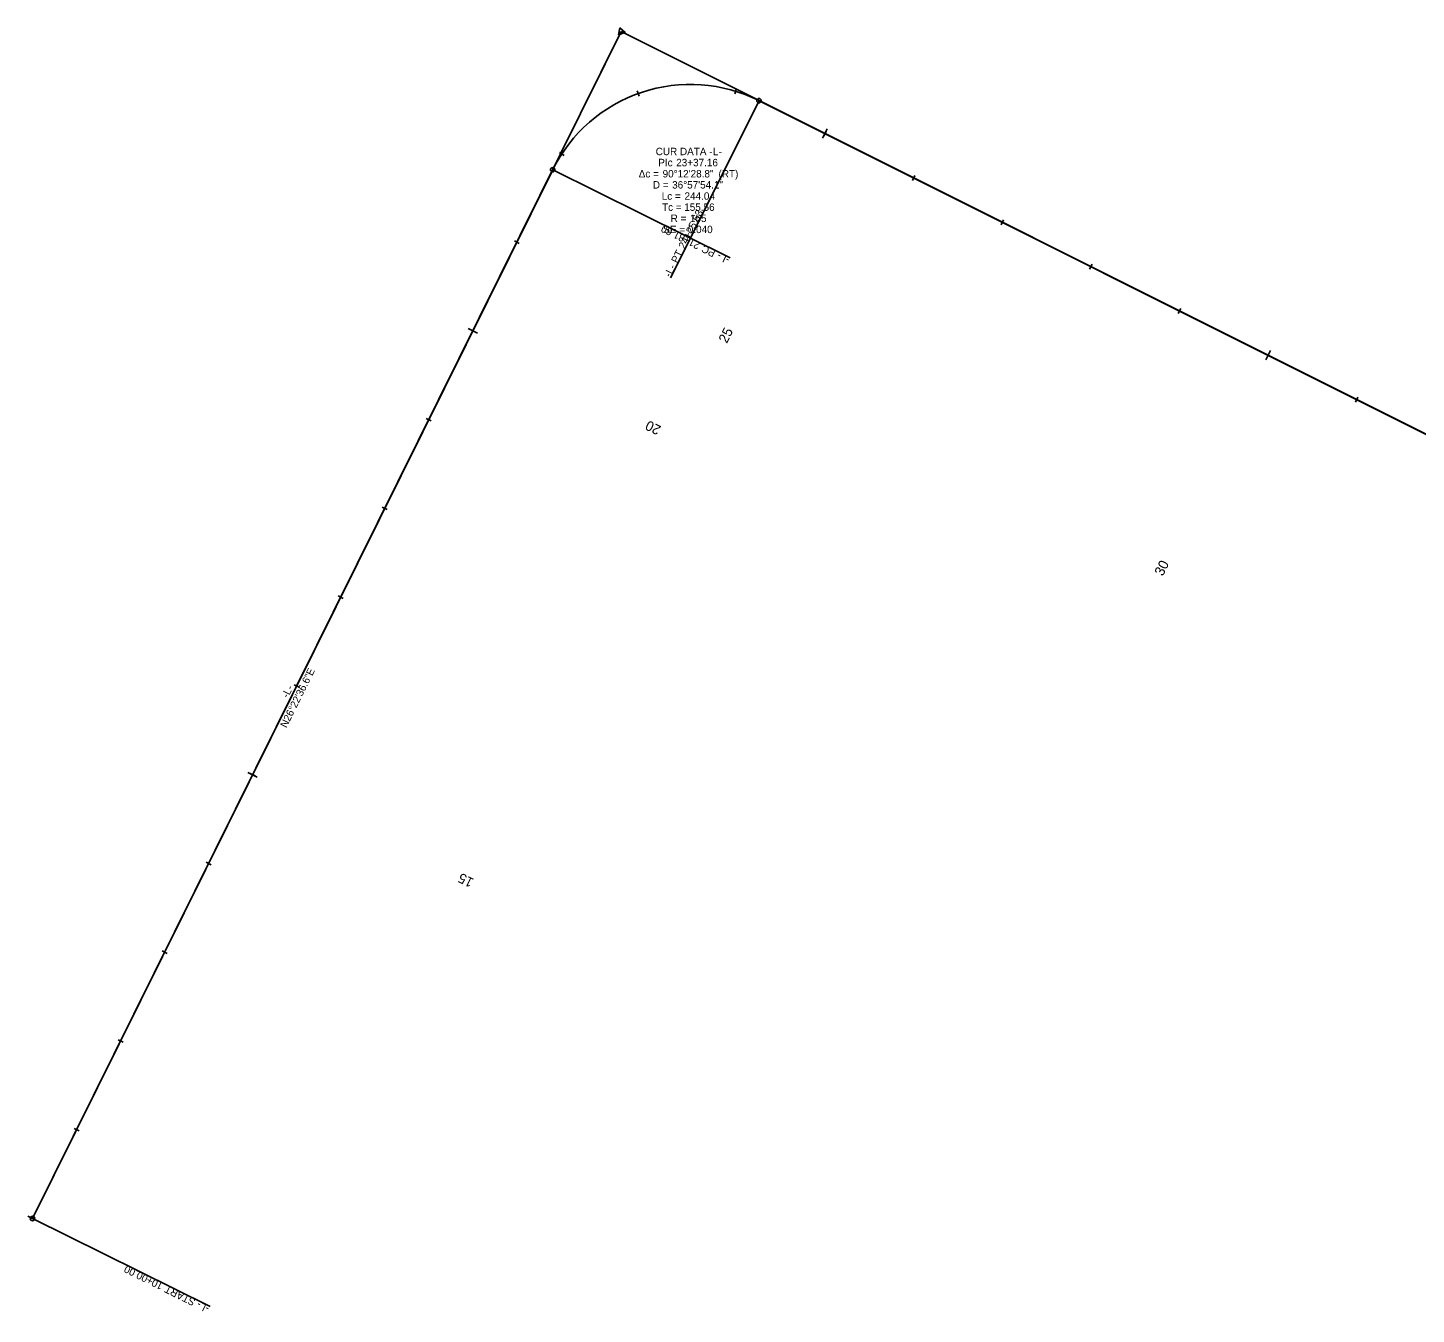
# Model space of a CAD drawing. Extents: x 2245492 to 2251120, y 200065 to 203543.
# Drawn here: x 2245492 to 2246893, y 202244 to 203543 of the extents above; entities that cross this region are included whole.
import ezdxf

# ---------------------------------------------------------------- set-up
doc = ezdxf.new("R2010")
doc.units = 0
for name, color, linetype in [('Default', 7, 'Continuous'), ('E_NCDOT_Terrain_Model_Breakline', 7, 'Continuous'), ('E_NCDOT_Terrain_Model_Contour_Minor', 7, 'Continuous'), ('E_NCDOT_Terrain_Model_Flow_Arrows', 7, 'Continuous'), ('E_NCDOT_Terrain_Model_Hole', 7, 'Continuous'), ('E_NCDOT_Terrain_Model_Points_High', 7, 'Continuous'), ('E_NCDOT_Terrain_Model_Points_Low', 7, 'Continuous'), ('E_NCDOT_Terrain_Model_Spot_Elevation', 7, 'Continuous'), ('E_NCDOT_Terrain_Model_Triangle_Vertices', 7, 'Continuous')]:
    doc.layers.add(name, color=color, linetype=linetype)

msp = doc.modelspace()

# ---------------------------------------------------------------- linework, layer by layer
at = {"layer": 'Default'}
for p, q in [((2246091.1, 203538.6), (2246059.1, 203474.1)), ((2246091.1, 203538.6), (2246155.5, 203506.3)), ((2246091.1, 203538.6), (2246091.1, 203538.6)), ((2245815.4, 202982.5), (2245785.4, 202922.1))]:
    msp.add_line(p, q, dxfattribs=at)
msp.add_lwpolyline([(2246089.8, 203542.5), (2246088.4, 203535.4), (2246095.2, 203537.7)], close=True, dxfattribs=at)
at = {"layer": 'E_NCDOT_Terrain_Model_Contour_Minor'}
for p, q in [((2245497.1, 202340.6), (2246091.1, 203538.6)), ((2246091.1, 203538.6), (2250670.6, 201246.8))]:
    msp.add_line(p, q, dxfattribs=at)
msp.add_arc((2246160.9, 203330.3), 155, 63.4152, 153.6232, dxfattribs=at)
at = {"layer": 'E_NCDOT_Terrain_Model_Flow_Arrows'}
for p, q in [((2246299.1, 203440.4), (2246294.4, 203430.9)), ((2245936.6, 203238.9), (2245946.1, 203234.2)), ((2246746.3, 203216.7), (2246741.5, 203207.2)), ((2245714.4, 202790.9), (2245723.9, 202786.2)), ((2245492.3, 202343), (2245501.8, 202338.3))]:
    msp.add_line(p, q, dxfattribs=at)
at = {"layer": 'E_NCDOT_Terrain_Model_Hole'}
for p, q in [((2246230.2, 203468.9), (2246140.7, 203290.1)), ((2246022, 203399.2), (2246201.2, 203310.3)), ((2245497.1, 202340.6), (2245676.2, 202251.8))]:
    msp.add_line(p, q, dxfattribs=at)
for centre in [(2246230.2, 203468.9), (2246022, 203399.2), (2245497.1, 202340.6)]:
    msp.add_circle(centre, 2.25, dxfattribs=at)
at = {"layer": 'E_NCDOT_Terrain_Model_Spot_Elevation'}
for p, q in [((2246207.3, 203481.1), (2246205.7, 203475.8)), ((2246107.3, 203478.7), (2246109.2, 203473.5)), ((2246298, 203438.1), (2246295.5, 203433.2)), ((2246028.8, 203416.7), (2246033.5, 203413.6)), ((2246387.4, 203393.4), (2246384.9, 203388.4)), ((2246476.8, 203348.6), (2246474.4, 203343.7)), ((2245983.3, 203327.3), (2245988.2, 203324.9)), ((2246566.3, 203303.9), (2246563.8, 203298.9)), ((2246655.7, 203259.1), (2246653.2, 203254.2)), ((2246834.5, 203169.6), (2246832.1, 203164.7)), ((2245894.4, 203148.1), (2245899.4, 203145.7)), ((2245850, 203058.5), (2245855, 203056.1)), ((2245805.6, 202969), (2245810.5, 202966.5)), ((2245761.2, 202879.4), (2245766.1, 202876.9)), ((2245716.7, 202789.8), (2245721.7, 202787.3)), ((2245672.3, 202700.2), (2245677.2, 202697.7)), ((2245627.9, 202610.6), (2245632.8, 202608.2)), ((2245583.4, 202521), (2245588.4, 202518.6)), ((2245539, 202431.4), (2245544, 202429))]:
    msp.add_line(p, q, dxfattribs=at)
at = {"layer": 'E_NCDOT_Terrain_Model_Triangle_Vertices'}
for p, q in [((2246230.2, 203468.9), (2250532.4, 201316)), ((2245497.1, 202340.6), (2246022, 203399.2))]:
    msp.add_line(p, q, dxfattribs=at)
msp.add_arc((2246160.9, 203330.3), 155, 63.4152, 153.6232, dxfattribs=at)

# ---------------------------------------------------------------- texts
at = {"layer": 'E_NCDOT_Terrain_Model_Breakline'}
for s, p in [('CUR DATA -', (2246125.9, 203413.9)), ('PIc ', (2246128.5, 203402.7)), ('23+37.16', (2246146.6, 203402.7)), ('L', (2246183.7, 203413.9)), ('-', (2246189.5, 203413.9)), ('Δc = ', (2246108.8, 203391.4)), ('90°12\'28.8"', (2246132.9, 203391.4)), (' (RT)', (2246186.5, 203391.4)), ('D = ', (2246123, 203380.2)), ('36°57\'54.1"', (2246142.5, 203380.2)), ('Lc = ', (2246132, 203368.9)), ('244.04', (2246155, 203368.9)), ('Tc = ', (2246132.3, 203357.7)), ('R = ', (2246141, 203346.4)), ('155.56', (2246154.7, 203357.7)), ('155', (2246160.5, 203346.4)), ('SE = 0.040', (2246133.5, 203335.2))]:
    msp.add_text(s, height=7.5, dxfattribs=at).set_placement(p)
at = {"layer": 'E_NCDOT_Terrain_Model_Hole'}
for s, rotation, p in [('24+25.63', 63.4152, (2246155.1, 203318.7)), ('21+81.60', 153.6232, (2246171.5, 203325.1)), ('PT', 63.4152, (2246147.8, 203304.2)), ('PC', 153.6232, (2246187.1, 203317.3)), ('- ', 153.6232, (2246192.8, 203314.5)), ('L', 153.6232, (2246198.1, 203311.9)), ('L', 63.4152, (2246142.3, 203293.2)), ('- ', 63.4152, (2246144.9, 203298.4)), ('-', 153.6232, (2246201.2, 203310.3)), ('-', 63.4152, (2246140.7, 203290.1)), ('10+00.00', 153.6232, (2245629.6, 202274.9)), ('START', 153.6232, (2245662.2, 202258.7)), ('- ', 153.6232, (2245667.9, 202255.9)), ('L', 153.6232, (2245673.1, 202253.3)), ('-', 153.6232, (2245676.2, 202251.8))]:
    msp.add_text(s, height=7.5, rotation=rotation, dxfattribs=at).set_placement(p)
at = {"layer": 'E_NCDOT_Terrain_Model_Points_High'}
for s, p in [('N26°22\'36.6"E', (2245753.3, 202835.3)), ('-', (2245758.9, 202873.7)), ('L', (2245756.3, 202868.4)), ('-', (2245754.8, 202865.3))]:
    msp.add_text(s, height=7.5, rotation=63.6232, dxfattribs=at).set_placement(p)
at = {"layer": 'E_NCDOT_Terrain_Model_Points_Low'}
for s, rotation, p in [('25', 63.4152, (2246197.7, 203223.3)), ('20', 153.6232, (2246132.1, 203139.9)), ('30', 63.4152, (2246637.6, 202988.4)), ('15', 153.6232, (2245943.1, 202683.1))]:
    msp.add_text(s, height=10, rotation=rotation, dxfattribs=at).set_placement(p)

doc.saveas('drawing.dxf')
